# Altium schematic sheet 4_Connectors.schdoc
size 307 x 218 mm; Symbol: Artery_A4; Device: Artery_A4; @Project Name: AT-START-M416; @Page Count: 4; @Create Date: 2024-11-11; Company: Artery Technology; Drawed: SD; Version: 1.1; Page Size: A4; @Update Date: 2024-11-14; @Page No: 4; @Schematic Name: AT-START-M416-V1.1; @Page Name: Connectors; Title Block Position: 3; Width: 1170; Height: 825; Region Start: 1; X Region Count: 6; Y Region Count: 4; Blade Width: 10; @Board Name: AT-START-M416-V1.1; @Create Time: 14:16:06; @Update Time: 13:53:49
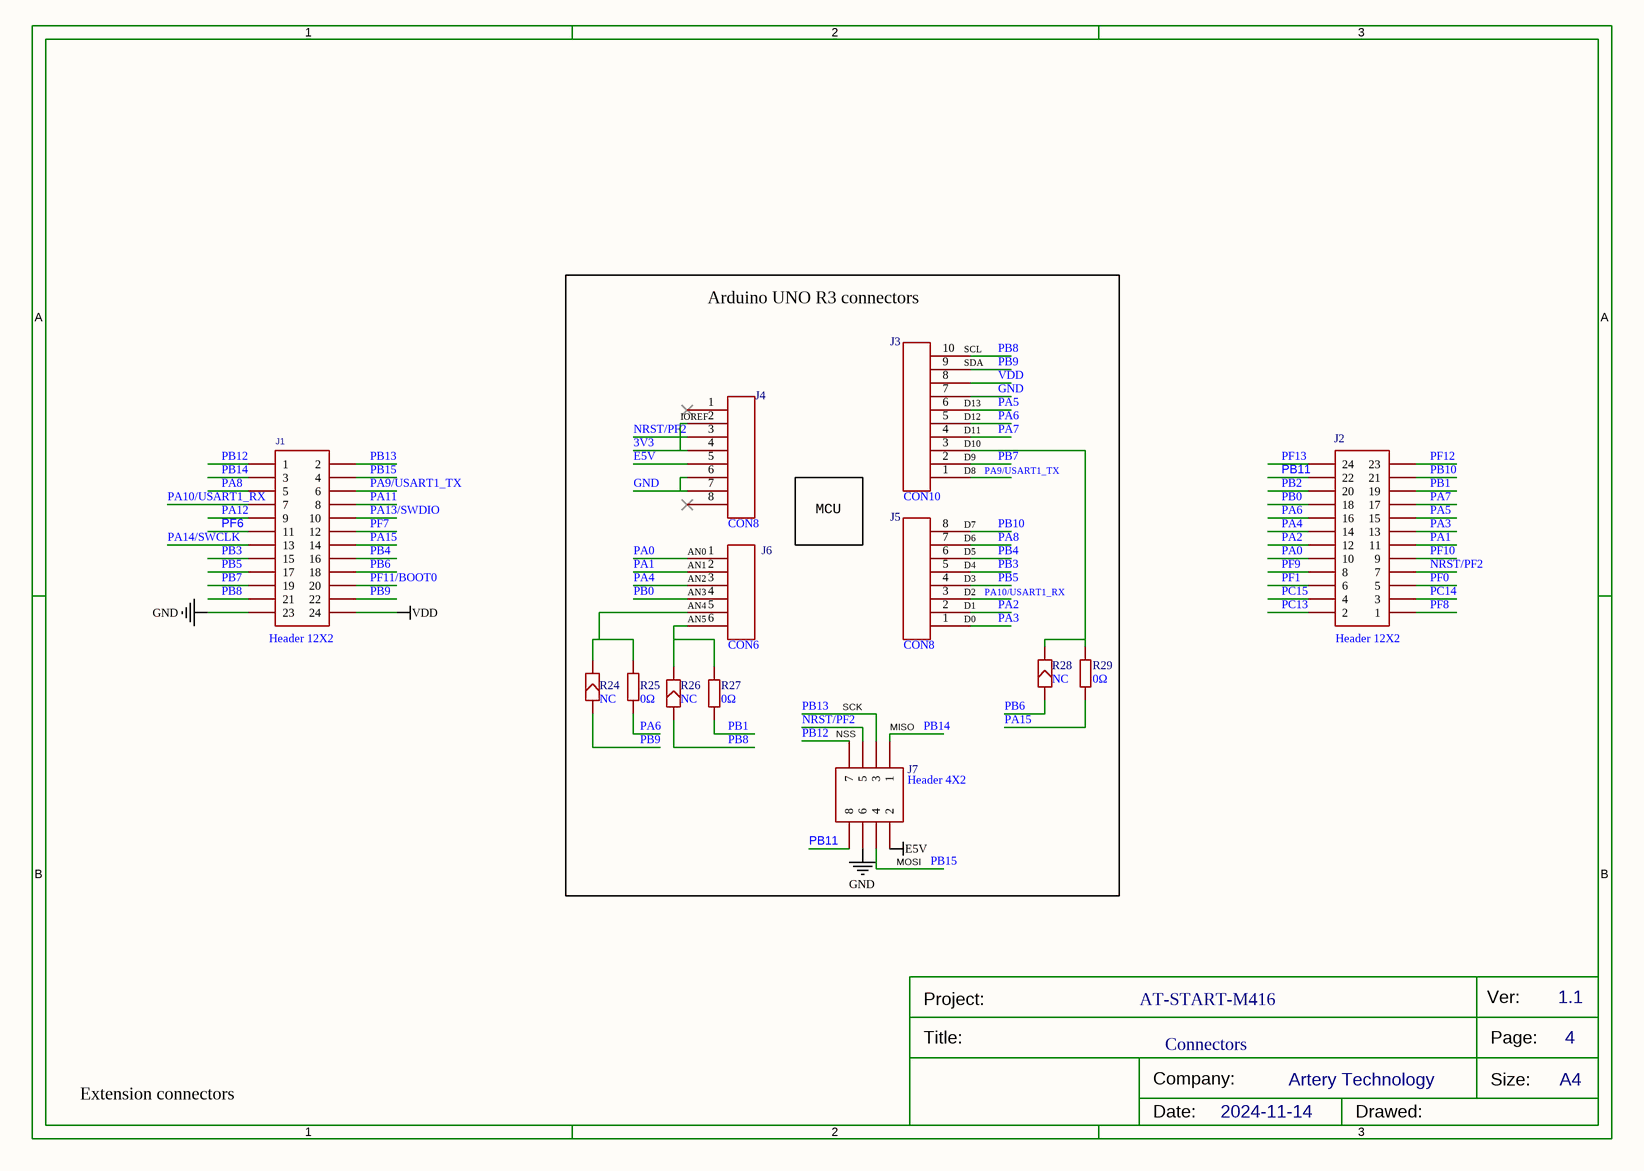
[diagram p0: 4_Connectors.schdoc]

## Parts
J1  Header 12X2  [HEAD2*12]
J2  Header 12X2  [HEAD2*12]
J3  CON10  [HDR1X10 - 2#]
J4  CON8  [HDR1X8 - 2#]
J5  CON8  [HDR1X8 - 2#]
J6  CON6  [HDR1X6 -2#]
J7  Header 4X2  [HDR2X4]
R24  NC  [SB-PAD_2]
R25  0Ω  [SB-PAD_2]
R26  NC  [SB-PAD_2]
R27  0Ω  [SB-PAD_2]
R28  NC  [SB-PAD_2]
R29  0Ω  [SB-PAD_2]

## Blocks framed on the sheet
Arduino UNO R3 connectors: J3-J7 R24-R29

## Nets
E5V: J4.5 J7.2
GND: J1.23 J3.7 J4.6 J4.7 J7.6
VDD: J1.24 J3.8
3V3: J4.2 J4.4
NRST/PF2: J2.7 J4.3 J7.5
PA0: J2.10 J6.1
PA1: J2.11 J6.2
PA2: J2.12 J5.2
PA3: J2.13 J5.1
PA4: J2.14 J6.3
PA5: J2.15 J3.6
PA6: J2.16 J3.5 R25.1
PA7: J2.17 J3.4
PA8: J1.5 J5.7
PA9/USART1_TX: J1.6 J3.1
PA10/USART1_RX: J1.7 J5.3
PA11: J1.8
PA12: J1.9
PA13/SWDIO: J1.10
PA14/SWCLK: J1.13
PA15: J1.14 R29.1
PB0: J2.18 J6.4
PB1: J2.19 R27.1
PB2: J2.20
PB3: J1.15 J5.5
PB4: J1.16 J5.6
PB5: J1.17 J5.4
PB6: J1.18 R28.1
PB7: J1.19 J3.2
PB8: J1.21 J3.10 R26.1
PB9: J1.22 J3.9 R24.1
PB10: J2.21 J5.8
PB11: J2.22 J7.8
PB12: J1.1 J7.7
PB13: J1.2 J7.3
PB14: J1.3 J7.1
PB15: J1.4 J7.4
PC13: J2.2
PC14: J2.3
PC15: J2.4
PF0: J2.5
PF1: J2.6
PF6: J1.11
PF7: J1.12
PF8: J2.1
PF9: J2.8
PF10: J2.9
PF11/BOOT0: J1.20
PF12: J2.23
PF13: J2.24
NetJ3_3: J3.3 R28.2 R29.2
NetJ6_5: J6.5 R24.2 R25.2
NetJ6_6: J6.6 R26.2 R27.2

Not connected (* = marked no-connect by the designer): J4 1* 8*

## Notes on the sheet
- (near J3) SCL
- (near J3) SDA
- (near J4) IOREF
- (near J3) D10
- (near J3) D11
- (near J3) D12
- (near J3) D13
- MCU
- (near J3) D8
- (near J3) D9
- (near J6) AN0
- (near J6) AN1
- (near J6) AN2
- (near J5) D3
- (near J5) D4
- (near J5) D5
- (near J5) D6
- (near J5) D7
- (near J6) AN3
- (near J6) AN4
- (near J6) AN5
- (near J5) D0
- (near J5) D1
- (near J5) D2
- SCK
- (near J7) NSS
- (near J7) MISO
- (near J7) MOSI
- AT-START-M416
- Extension connectors

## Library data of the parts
J1 J2 = Header 12X2: Add into BOM: yes
J3 = CON10: Symbol: CON10_0; Add into BOM: yes
J4 J5 = CON8: Add into BOM: yes
J6 = CON6: Add into BOM: yes
J7 = Header 4X2: Add into BOM: yes
R24 R26 R28 = SB_PAD: Symbol: SB-PAD; Convert to PCB: yes
R25 R27 R29 = 0603WAF0000T5E: Manufacturer: UNI-ROYAL(厚声); Add into BOM: yes; Tolerance: ±1%; Power(Watts): 100mW; Overload Voltage (Max): 75V; Origin Footprint: SB-PAD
